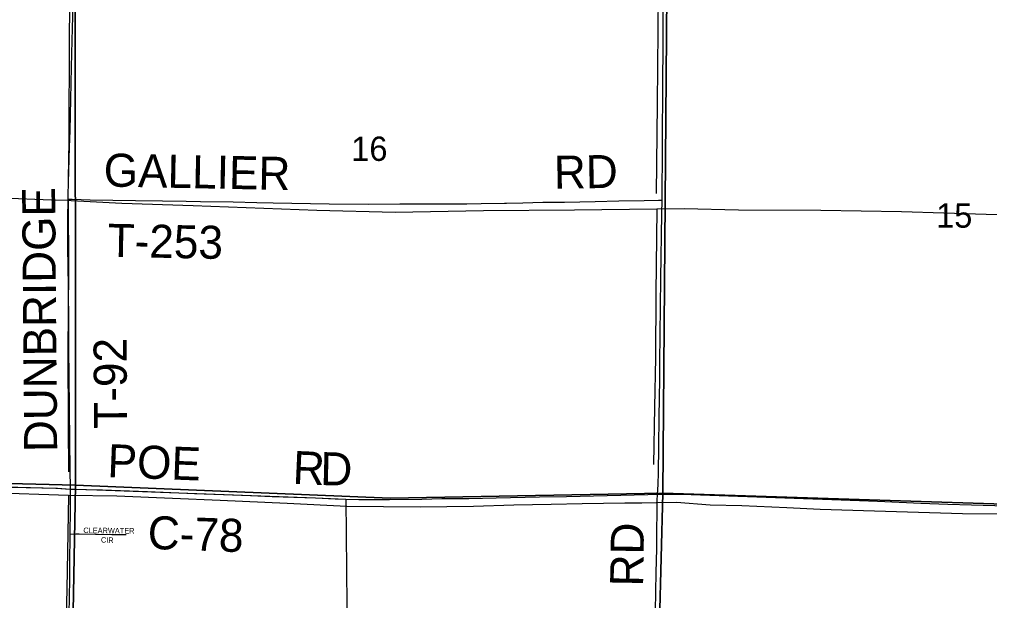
# Model space of a CAD drawing. Extents: x 1443599 to 1910620, y 1028088 to 1361369.
# Drawn here: x 1663185 to 1671995, y 1234081 to 1239361 of the extents above; entities that cross this region are included whole.
import ezdxf

# ---------------------------------------------------------------- set-up
doc = ezdxf.new("R2010")
doc.units = 0
for name, color, linetype in [('GM_X_City_Street', 7, 'Continuous'), ('GM_X_City_Street_Text', 7, 'Continuous'), ('GM_X_Corporation', 7, 'Continuous'), ('GM_X_County_Road', 7, 'Continuous'), ('GM_X_County_Road_Text', 7, 'Continuous'), ('GM_X_Minor_River', 7, 'Continuous'), ('GM_X_Section', 7, 'Continuous'), ('GM_X_Section_Text', 7, 'Continuous'), ('GM_X_Township_Road', 7, 'Continuous'), ('GM_X_Township_Road_Text', 7, 'Continuous')]:
    doc.layers.add(name, color=color, linetype=linetype)

msp = doc.modelspace()

# ---------------------------------------------------------------- linework, layer by layer
at = {"layer": 'GM_X_City_Street'}
for points in [[(1663645.9, 1234685.6), (1663649.9, 1234909.3), (1663649.2, 1234984), (1663649.8, 1235094.5)], [(1663633, 1233765.2), (1663634, 1233814.5), (1663635.1, 1233863.8), (1663639.8, 1234093.8), (1663641.8, 1234294.6), (1663643.4, 1234452.6), (1663645.2, 1234648.4), (1663645.9, 1234685.6)], [(1663645.9, 1234685.6), (1663696.2, 1234685.9), (1663729, 1234686.1), (1664024.6, 1234681.7), (1664156, 1234681.3)]]:
    msp.add_lwpolyline(points, dxfattribs=at)
at = {"layer": 'GM_X_Corporation'}
msp.add_lwpolyline([(1662128.3, 1235138.4), (1663515, 1235101.2), (1663649.8, 1235094.5), (1663686.5, 1235093.4), (1663889.3, 1235087.5), (1664963.1, 1235046.9), (1665872.6, 1235013.3), (1666148.7, 1235002.4), (1666174, 1232434.6), (1666253.2, 1232433.3), (1666242, 1231409.2), (1666202.8, 1231409.5), (1666209.8, 1231126), (1665477.8, 1231138.4), (1664743.7, 1231157.5), (1664740.7, 1230682.5), (1664904.7, 1230677.9), (1664906.1, 1230203.1), (1664866.8, 1228514.3), (1666194.9, 1228494.3), (1666148, 1226883.9)], dxfattribs=at)
at = {"layer": 'GM_X_County_Road'}
for points in [[(1669021.6, 1237719.1), (1669021.8, 1237734.9), (1669024.9, 1238194.5), (1669028.8, 1238818.2), (1669029.6, 1239080.8), (1669030.4, 1239172.7), (1669034.1, 1239743.9), (1669037, 1240026.2), (1669041.4, 1240338.4)], [(1668980, 1235046.7), (1668983.2, 1235086.4), (1668985.7, 1235138.8), (1668988.7, 1235240.3), (1668992.4, 1235479.9), (1668995.2, 1235745.8), (1669000.4, 1236093.7), (1669001.6, 1236244.7), (1669010.9, 1237006.3), (1669019.9, 1237593.8), (1669021.6, 1237719.1)], [(1662978.6, 1235115.1), (1663104.3, 1235111.8), (1663530.3, 1235100.8), (1663649.8, 1235094.5)], [(1663649.8, 1235094.5), (1663939.8, 1235086.1), (1664349.3, 1235071.3), (1664775.1, 1235054.4), (1665037.2, 1235044), (1665283, 1235035.8), (1665479.4, 1235027.7), (1665676.1, 1235020.4), (1665872.6, 1235013.3), (1666052.8, 1235006.5), (1666148.7, 1235002.4)], [(1666148.7, 1235002.4), (1666266, 1235000.3), (1666323, 1234999.7)], [(1666323, 1234999.7), (1666397.4, 1234998.8), (1666545.2, 1235000.4), (1666840.7, 1235003.5), (1667021.3, 1235007), (1667267.6, 1235009.6), (1667513.9, 1235013), (1667907.9, 1235022.2), (1668154.1, 1235027.5), (1668892.8, 1235045.5), (1668980, 1235046.7)], [(1668915.3, 1231070.6), (1668915.5, 1231094.2), (1668916.3, 1231193.8), (1668917.9, 1231298.7), (1668917.8, 1231410.4), (1668921.1, 1231590.9), (1668923.4, 1231846.9), (1668927.3, 1232119.4), (1668935.5, 1232582.2), (1668941.5, 1232953.1), (1668953.1, 1233557), (1668956.5, 1233809.8), (1668960.5, 1233983.7), (1668968.2, 1234334.9), (1668972.9, 1234551.4), (1668974.6, 1234705.7), (1668976.4, 1234892.7), (1668976.7, 1234994.6), (1668979.2, 1235037.3), (1668980, 1235046.7)], [(1668980, 1235046.7), (1669040.4, 1235047.5), (1669171.7, 1235046.9), (1669286.5, 1235044.3), (1670221.9, 1235012.1), (1670648.5, 1234997.3), (1670976.6, 1234985), (1671370.3, 1234966.8), (1671616.4, 1234956.6), (1671829.8, 1234949.8), (1672043.3, 1234945.6), (1672404.4, 1234938), (1672995.4, 1234924.8), (1673422.2, 1234916.9), (1673832.4, 1234904.7), (1674193.4, 1234892), (1674287, 1234889.4)]]:
    msp.add_lwpolyline(points, dxfattribs=at)
at = {"layer": 'GM_X_Minor_River'}
for points in [[(1669051.5, 1250481), (1669052.3, 1248694.8), (1669043.8, 1247833.8), (1669040.6, 1246731.8), (1669047, 1245547.2), (1669030.8, 1243991.9), (1669015.8, 1243111), (1669014.1, 1242133.4), (1669004.4, 1241651.8), (1668995.8, 1240784.8), (1668991, 1240263), (1668975.6, 1238593.1), (1668968.5, 1237780.3)], [(1663709, 1247445.4), (1663717.9, 1245553.4), (1663710.9, 1244672.3), (1663706.9, 1244248.8), (1663690.7, 1242904.2), (1663675.8, 1241746.2), (1663661.8, 1241112.2), (1663654.6, 1240576.4), (1663650.8, 1240301.5), (1663638.1, 1239219.8), (1663634.7, 1238252.2), (1663629.1, 1237915.1)], [(1672708.6, 1237576.7), (1671965.4, 1237588), (1671194.4, 1237612.1), (1670461.3, 1237625.1), (1669715.8, 1237626.4), (1669223.1, 1237638.5), (1668972.4, 1237635.6), (1668226.7, 1237628.9), (1667398.7, 1237620.5), (1666598.6, 1237607.2), (1665887.6, 1237623.6), (1664762.4, 1237665.8), (1664115.7, 1237688.4), (1663654.3, 1237713.4), (1663627.5, 1237716.4), (1663475.2, 1237718.8), (1663026.7, 1237735.6), (1662365.6, 1237744.5), (1661684.7, 1237764), (1661206, 1237773.7), (1660589, 1237787.3), (1660110.4, 1237801), (1659813.9, 1237805.5), (1659663.1, 1237809.5)], [(1663627.5, 1237716.4), (1663629.7, 1237090), (1663626.5, 1236341.2), (1663629.5, 1235670.6), (1663631.5, 1235249)], [(1668972.4, 1237635.6), (1668964.7, 1236871), (1668962.2, 1236286.8), (1668953.4, 1235837.4), (1668944.6, 1235317.7)], [(1672174.6, 1234865.8), (1671749.8, 1234869.9), (1670948.8, 1234892.9), (1670456.2, 1234909), (1670154, 1234923.7), (1669745.7, 1234941.4), (1669459.2, 1234947.6), (1669153.3, 1234972.4), (1668966.8, 1234969.7), (1668836.4, 1234965.4), (1668684.1, 1234965.8), (1668295.2, 1234960.9), (1668014.3, 1234952.8), (1667675.5, 1234946.5), (1667308.4, 1234936.9), (1666825.2, 1234928.7), (1666157.9, 1234935.7), (1665615.5, 1234961.3), (1665009.1, 1234990.7), (1664574.6, 1235007.2), (1664070.2, 1235029.6), (1663631.5, 1235036.2), (1662910.6, 1235058.8)], [(1663631.5, 1235036.2), (1663617.3, 1234183.4), (1663599.5, 1233559.5), (1663598.4, 1233238.3), (1663596.3, 1232951.3), (1663585.3, 1232564.2), (1663582.3, 1232178.8), (1663567.9, 1231809.8), (1663525.4, 1231392.4)]]:
    msp.add_lwpolyline(points, dxfattribs=at)
at = {"layer": 'GM_X_Section'}
for points in [[(1658369.4, 1240479.4), (1663692.8, 1240369.8), (1663695.4, 1235129.4), (1658278.7, 1235264.2), (1658232.2, 1238116.1)], [(1663692.8, 1240369.8), (1669071.1, 1240358.7), (1669028.9, 1235056.7), (1666551.3, 1235011.8), (1663695.4, 1235129.4)], [(1669071.1, 1240358.7), (1674344.8, 1240300.7), (1674346.5, 1240272.7), (1674285.2, 1234886.9), (1669028.9, 1235056.7)], [(1658278.7, 1235264.2), (1663695.4, 1235129.4), (1663596.4, 1229891.8), (1658343.9, 1230008.1)], [(1669028.9, 1235056.7), (1668893.2, 1229767.9), (1663596.4, 1229891.8), (1663695.4, 1235129.4), (1666551.3, 1235011.8)], [(1669028.9, 1235056.7), (1674285.2, 1234886.9), (1674205.9, 1229631.8), (1668893.2, 1229767.9)]]:
    msp.add_lwpolyline(points, close=True, dxfattribs=at)
at = {"layer": 'GM_X_Township_Road'}
for points in [[(1663626.9, 1237727.5), (1663627.3, 1237768), (1663633.4, 1237984.7), (1663641, 1238201), (1663644.8, 1238352), (1663651.2, 1238637.5), (1663658.2, 1238926.3), (1663664.7, 1239169.1), (1663672.8, 1239497.3), (1663677.8, 1239759.9), (1663684.4, 1240061.7), (1663690.1, 1240278.3), (1663692, 1240356)], [(1663649.8, 1235094.5), (1663646, 1235276.8), (1663643.3, 1235526.3), (1663637.5, 1236123.7), (1663634.4, 1236360), (1663633.3, 1236576.7), (1663630.4, 1236937.5), (1663625.3, 1237288.9), (1663624.7, 1237548.2), (1663626.9, 1237727.5)], [(1663626.9, 1237727.5), (1663664.4, 1237726.7), (1663828.7, 1237723), (1664239.6, 1237716.7), (1664486.1, 1237713.2), (1664699.7, 1237708.8), (1664831.2, 1237706.3), (1665127, 1237702.2), (1665340.5, 1237697.1), (1665488.4, 1237693.4), (1665997.8, 1237685.4), (1666359.4, 1237683), (1666638.8, 1237684.3), (1666868.9, 1237685), (1667016.8, 1237685.9), (1667247, 1237685.6), (1667378.4, 1237687.7), (1667589.7, 1237692.1)], [(1667589.7, 1237692.1), (1667608.5, 1237692.5), (1667756.4, 1237695.4), (1667937.1, 1237699), (1668134.4, 1237701.5), (1668413.8, 1237706.2), (1668627.3, 1237711.7), (1668857.4, 1237715.4), (1668988.9, 1237718.4), (1669021.6, 1237719.1)]]:
    msp.add_lwpolyline(points, dxfattribs=at)

# ---------------------------------------------------------------- texts
at = {"layer": 'GM_X_City_Street_Text'}
for s, rotation, p in [('CLEARWATER', 359.39027, (1663765.8, 1234694.3)), ('CIR', 357.39879, (1663924.9, 1234608.4))]:
    msp.add_text(s, height=50, rotation=rotation, dxfattribs=at).set_placement(p)
at = {"layer": 'GM_X_County_Road_Text'}
for s, rotation, p in [('POE', 357.81264, (1663981.3, 1235203.3)), ('R', 357.50129, (1665662.9, 1235141.5)), ('D', 358.58927, (1665915.2, 1235130.6)), ('C-78', 357.94207, (1664346.4, 1234551.3)), ('RD', 89.02673, (1668848.5, 1234207.4))]:
    msp.add_text(s, height=300, rotation=rotation, dxfattribs=at).set_placement(p)
at = {"layer": 'GM_X_Section_Text'}
for s, p in [('16', (1666198.8, 1238075.4)), ('15', (1671509.6, 1237468.8))]:
    msp.add_text(s, height=221, rotation=0.00001, dxfattribs=at).set_placement(p)
at = {"layer": 'GM_X_Township_Road_Text'}
for s, rotation, p in [('GALLIER', 358.87827, (1663948.4, 1237843.3)), ('RD', 0.98704, (1668041.4, 1237821.3)), ('DUNBRIDGE', 90.46539, (1663528.7, 1235431.2)), ('T-253', 358.88139, (1663983.6, 1237204.7)), ('T-92', 90.35349, (1664163.1, 1235642.9))]:
    msp.add_text(s, height=300, rotation=rotation, dxfattribs=at).set_placement(p)

doc.saveas('drawing.dxf')
